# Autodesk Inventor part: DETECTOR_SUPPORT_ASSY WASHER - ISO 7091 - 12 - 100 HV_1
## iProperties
Shininess: 64.0
Length Units: 11272
Angle Units: 11279
Time Units: 11290
Mass Units: 11286
Length Display Precision: 3
Angle Display Precision: 2
Compacted: True
Part Number: DETECTOR_SUPPORT_ASSY WASHER - ISO 7091 - 12 - 100 HV_1
Document SubType Name: Modeling
Created: 2004-08
Designer: John Blackburn
Material: MILD_STEEL
Manufacturer: Standard
Standards Organization: Custom
Density: 0.0
Volumn: 0.0
Area: 0.0
PropertySet Name: Model Information
Control State: 0
Master: False
Checked Out: False
Author: John Blackburn
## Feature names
1. Base1
